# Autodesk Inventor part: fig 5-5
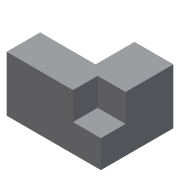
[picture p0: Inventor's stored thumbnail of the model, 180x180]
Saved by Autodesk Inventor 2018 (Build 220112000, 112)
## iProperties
Created: 2010-02
Part Number: fig 5-5
Document SubType Name: Modeling
Designer: CADSoft
Density: 1 g/cm^3
Material: Generic
Appearance: Default
Author: CADSoft
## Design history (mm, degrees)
sketch "Sketch1"
  geometry: L1 (0, 26.227)-(0, 12.145); L2 (0, 12.145)-(-20.026, 12.145); L3 (-20.026, 12.145)-(-20.026, 0); L4 (-20.026, 0)-(14.083, 0); L5 (14.083, 0)-(14.083, 26.227); L6 (14.083, 26.227)-(0, 26.227); 1 further point
  constraints: 12 end point
extrude "Extrusion1" new body sketch "Sketch1" distance "d0" = 20; taper "d1" = 0 deg
sketch "Sketch2"
  geometry: L1 (14.083, 0)-(3.983, 0); L2 (3.983, 0)-(3.983, 8.922); L3 (3.983, 8.922)-(14.083, 8.922); L4 (14.083, 8.922)-(14.083, 0); 1 further point
  constraints: 8 end point
extrude "Extrusion2" cut sketch "Sketch2" distance "d2" = 10; taper "d3" = 0 deg
body "Solid1"
